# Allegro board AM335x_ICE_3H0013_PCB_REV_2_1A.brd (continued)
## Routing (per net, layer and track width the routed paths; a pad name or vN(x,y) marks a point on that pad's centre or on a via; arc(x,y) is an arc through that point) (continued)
N28737675: length 7.4
  TOP w0.121: U14.G17 33.05,42.45 32.71,42.11 31.47,42.11 30.86,41.5 30.13,41.5 29.97,41.34 29.97,40.93 28.8,39.75 R58.2
N28753994: length 11.2
  TOP w0.121: v1(22.35,97.59) 21.03,96.27 20.07,96.27 19.43,95.63 SW1.4
  BOTTOM w0.121: v1(22.35,97.59) U25.3 23.96,97.57 25.74,97.57 R100.2
N28754074: length 8.4
  TOP w0.121: v1(23.24,94.36) 24,94.36 24.51,93.85 SW1.8
  BOTTOM w0.121: U25.5 21.42,96.94 21.84,96.52 21.84,95.89 R87.2 22.1,95 22.48,94.61 22.99,94.61 v1(23.24,94.36)
N28785526: length 2.4
  BOTTOM w0.121: R112.2 J19.1
N28785533: length 2.7
  BOTTOM w0.121: 48.9,83.57 R110.2
N28944514: length 2.6
  BOTTOM w0.121: R114.2 61.47,84.33 J18.1
N28944521: length 2.7
  BOTTOM w0.121: R113.2 66.55,84.33 J18.3
N29141166: length 15.7
  TOP w0.121: U12.14 72.87,59.48 v1(72.34,58.95)
  BOTTOM w0.121: Y1.1 70.51,49.16 70.51,53.64 70.1,54.05 70.1,54.74 71.5,56.13 C89.2 71.5,58.11 v1(72.34,58.95)
N29141233: length 9.4
  TOP w0.121: v1(70.12,58.74) 69.38,59.48 U12.1
  BOTTOM w0.121: v1(70.12,58.74) 70.12,58.61 69.72,58.21 C90.2 68.83,56.9 Y1.2
N29141536: length 1.6
  TOP w0.121: R39.1 67.53,58.83 U12.2
N29149555: length 2.1
  TOP w0.121: R42.1 75.99,55.58 U12.8
N29149585: length 2.9
  TOP w0.121: U12.9 75.41,56.23 75.69,56.52 v1(75.69,56.9)
  BOTTOM w0.121: 75.44,58.04 75.44,57.15 v1(75.69,56.9)
N29149616: length 5.2
  TOP w0.121: v1(76.33,56.9) 75.69,57.53 U12.11
  BOTTOM w0.121: 74.3,58.04 74.3,57.53 75.44,56.39 75.82,56.39 v1(76.33,56.9)
N29208060: length 2.2
  TOP w0.121: J5.1 62.99,60.96 R37.1

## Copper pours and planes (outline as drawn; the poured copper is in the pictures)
DGND on TOP: 65.66,27.66 65.66,25.27 65.28,24.89 65.28,24.51 65.53,24.26 66.29,24.26 66.67,23.88 68.94,23.88 69.19,24.13 69.19,25.45 68.73,25.91 67.94,25.91 67.06,26.8 67.06,27.53 66.75,27.84 65.84,27.84
DGND on TOP: 41.17,22.62 40.64,22.1 38.73,22.1 36.91,23.92 36.91,25.93 37.18,26.2 38.14,26.2 38.99,25.34 40.93,25.34 41.17,25.11
DGND on TOP: 46.48,11.05 46.74,10.8 48.51,10.8 48.77,11.05 48.77,13.84 48.51,14.1 46.74,14.1 46.48,13.84
DGND on TOP: 67.31,60.58 74.8,60.58 75.56,59.82 74.68,58.93 67.31,58.93 67.06,59.18 67.06,60.33
DGND on TOP: 5.53,26.58 5.53,34.26 5.77,34.5 10.35,34.5 10.35,34.5 10.8,34.5 12.29,33.01 12.29,32.55 12.2,32.47 10.35,32.47 10.35,26.5 10.1,26.25 5.86,26.25
DGND on TOP: 40.26,54.23 40.39,54.1 40.39,52.2 39.75,51.56 38.48,51.56 38.1,51.94 38.23,52.07 38.23,53.72 38.86,54.36 38.99,54.23
DGND on TOP, BOTTOM: 53.39,51.91 53.39,52.87 53.75,53.24 54.19,53.24 54.34,53.09 54.34,52.84 53.83,52.33 53.83,52.33 53.73,52.23 53.73,51.91 53.7,51.87 53.42,51.87
DGND on BOTTOM: 37.34,46.86 37.34,45.34 37.97,44.7 37.97,44.2 37.72,43.94 36.96,43.94 36.7,43.69 36.7,42.93 36.96,42.67 37.34,42.67 37.34,42.16 37.47,42.04 38.35,42.04 38.42,42.1 39.12,41.4 40.13,41.4 40.51,41.78 41.27,41.78 42.29,40.77 42.93,40.77 42.93,48.26 40.77,48.26 40.01,47.5 39.12,47.5 38.73,47.88 38.35,47.88 38.23,47.75 38.23,47.24 38.1,47.12 37.59,47.12
DGND on BOTTOM: 36.14,54.05 35.87,54.32 35.87,55.12 37.5,56.75 37.5,58.71 36.6,57.81 35.36,57.81 35.36,58.23 36.32,59.19 40.2,59.19 40.69,59.68 40.69,63.43 36.9,63.43 36.07,64.26 36.07,64.26 35.14,65.19 33.1,65.19 32.41,65.88 32.41,67.33 32.73,67.64 32.89,67.64 32.89,72.9 33.08,73.09 33.15,73.03 33.15,73.53 33.4,73.79 34,73.79 35.56,72.22 35.56,71.37 36.45,70.48 36.45,66.93 37.21,66.17 43.18,66.17 43.43,66.42 44.32,66.42 44.32,66.89 47.29,69.86 47.83,69.86 47.82,69.86 54.72,69.86 55.84,70.98 60.75,70.98 61.4,70.33 63.11,70.33 66.66,66.78 66.66,63.4 67.98,62.08 75.08,62.08 76.27,60.89 76.27,56.46 75.08,56.46 74.54,56.99 74.54,58.67 73.58,59.63 67.24,59.63 63.09,63.78 63.09,67.58 62.44,68.24 48.89,68.24 47.29,66.64 47.29,65.12 45.98,63.81 44.32,63.81 44.32,60.71 45.34,60.71 46.1,59.94 46.1,59.69 44.32,57.91 44.32,56.77 44.07,56.52 43.31,56.52 43.08,56.29 43.08,55.82 41.31,54.05
DGND on BOTTOM: 68.63,59.49 72.57,59.49 73.28,58.78 73.28,45.72 72.26,44.7 67.82,44.7 66.8,45.72 66.8,50.42 65.53,51.69 65.53,52.83 66.04,53.34 66.04,56.9
DGND on BOTTOM: 63.25,6.35 63.75,6.35 64.39,6.99 64.77,6.99 65.79,8 65.79,8.26 65.53,8.51 63.12,8.51 62.99,8.38 62.99,6.6
DGND on BOTTOM: 49.15,10.8 49.66,11.3 49.66,12.95 45.72,12.95 45.59,12.83 45.59,11.18 45.97,10.8
DGND on BOTTOM: 43.97,44.55 44.12,44.55 44.68,45.11 47.42,45.11 47.32,45.21 50.8,45.21 55.2,49.61 58.5,49.61 59.24,48.87 61.31,48.87 61.79,48.39 62.97,48.39 62.97,48.38 63.42,48.38 65.72,46.09 66.42,46.09 66.58,45.93 66.58,44.84 66.55,44.81 68.76,42.59 68.76,37.95 68.15,37.34 67.82,37.34 67.31,36.83 67.31,35.31 69.62,35.31 69.62,33.76 68.15,33.76 68.11,33.73 66.5,33.73 66.12,34.11 66.12,37.52 62.69,40.94 62.69,42.38 61.62,43.45 57.71,43.45 56.24,41.98 56.24,39.1 56.29,39.1 56.83,38.56 56.83,35 56.52,34.69 56.88,34.33 56.88,31.34 57.95,30.27 58.63,30.95 67.59,30.95 67.59,30.13 67.06,29.59 64.9,29.59 64.01,28.7 57.45,28.7 53.85,32.3 53.85,40 51.89,41.96 47.74,41.96 47.34,42.36 47.34,42.47 47.17,42.47 46.2,43.43 44.7,43.43 44.42,43.15 44.02,43.15 43.87,43.31 43.87,44.45
DGND on BOTTOM: 40.16,11.96 40.16,9.33 40,9.17 40.02,9.17 39.17,8.32 39.17,4.82 40.14,3.85 43.2,3.85 44.16,4.82 44.16,7.86 43.67,8.36 43.67,11.96 43.47,12.16 40.37,12.16
DGND on LYR2_GND: 0.65,103.5 77.85,103.5 77.85,0.64 27.56,0.64 26.96,1.23 15.83,1.23 15.23,0.64 0.65,0.64
DGND on LYR4: 52.2,74.93 57.53,74.93 61.59,70.87 61.59,63.25 61.98,62.87 66.42,62.87 67.44,61.85 67.44,60.83 66.87,60.26 59.75,60.26 58.67,61.34 58.67,70.74 57.28,72.14 56.77,72.14 55.63,73.28 51.94,73.28 51.56,73.66 51.56,74.3
GND_EARTH on TOP: 1.4,0.76 1.4,5.08 2.03,5.72 3.68,5.72 4.19,5.21 4.19,3.56 3.17,2.54 3.17,0.76
GND_EARTH on TOP: 9.53,0.64 9.53,2.67 8.64,3.56 8.64,4.32 9.02,4.7 10.92,4.7 11.05,4.57 11.05,2.41 11.43,2.03 11.43,0.64
GND_EARTH on BOTTOM: 28.27,0.82 27.74,1.34 14.89,1.34 14.43,0.89 2.92,0.89 1.65,2.16 1.65,5.46 2.02,5.83 2.65,5.83 3.05,6.22 3.05,7.29 3.12,7.36 4.35,7.36 4.48,7.23 4.48,4.93 4.97,4.45 7.38,4.45 8.52,5.59 10.41,5.59 11.94,7.11 13.72,7.11 14.22,7.62 14.22,11.94 18.54,16.26 29.08,16.26 29.97,15.37 29.97,11.79 29.54,11.36 28.89,11.36 28.07,12.19 28.07,12.95 27.3,13.72 20.95,13.72 20.26,13.02 19.11,13.02 18.41,12.32 16.26,12.32 15.49,11.56 15.49,5.97 14.22,4.7 11.18,4.7 10.92,4.45 10.92,2.67 11.18,2.41 27.98,2.41 28.27,2.12 30.4,2.12 30.62,1.9 30.62,0.96 30.48,0.82
GND_EARTH on LYR2_GND: 1.27,2.03 2.16,1.14 13.34,1.14 14.2,2.01 30.14,2.01 30.48,1.67 30.48,0.51 27.56,0.51 27.05,1.02 15.75,1.02 15.24,0.51 1.18,0.51 0.64,1.05 0.64,24.81 0.72,24.89 1.02,24.89 1.27,24.64
GND_EARTH on LYR5_PWR: 0.77,24.89 1.02,24.89 1.27,24.64 1.27,3.19 3.31,1.14 13.34,1.14 13.97,1.78 27.94,1.78 28.32,2.16 30.35,2.16 30.48,2.03 30.48,0.51 27.56,0.51 27.05,1.02 15.75,1.02 15.24,0.51 0.91,0.51 0.66,0.76 0.66,24.78
GND_OSC1 on BOTTOM: 42.16,26.16 42.16,32.26 42.42,32.51 50.29,32.51 50.55,32.26 50.55,26.16 50.29,25.91 42.42,25.91
GNDA_ADC on LYR4: 39.62,37.34 39.88,37.08 40.39,37.08 40.64,37.34 40.64,39.75 41.15,40.26 41.15,40.51 41.02,40.64 40.26,40.64 39.62,40.01
GNDPROFI on LYR5_PWR: 1.27,25.15 5.59,25.15 6.1,25.65 6.1,33.27 6.6,33.78 10.92,33.78 11.43,34.29 11.43,37.08 12.83,38.48 18.67,38.48 20.7,40.51 20.7,45.34 17.02,49.02 9.4,49.02 8.89,49.53 8.89,53.59 9.4,54.1 18.54,54.1 19.05,53.59 19.05,52.58 19.56,52.07 23.62,52.07 24.13,52.58 24.13,57.15 23.62,57.66 17.02,57.66 16.51,58.17 16.51,60.96 16,61.47 7.92,61.47 7.65,61.2 7.65,57.04 6.88,56.27 4.97,56.27 4.7,56.01 1.27,56.01
V3_3D on TOP: 61.72,27.69 62.87,27.69 63.75,26.8 65.15,26.8 65.28,26.67 65.28,25.4 64.77,24.89 64.77,24.38 64.52,24.13 61.98,24.13 61.47,24.64 61.47,27.43
V3_3D on TOP: 67.18,56.39 66.67,55.88 66.67,55.24 66.17,54.74 66.17,54.48 66.29,54.36 68.45,54.36 69.34,55.24 69.34,55.37 69.47,55.37 69.47,56.39
V3_3D on BOTTOM: 64.9,25.78 63.12,25.78 62.99,25.91 62.99,27.18 62.74,27.43 61.85,27.43 61.72,27.3 61.72,24.51 61.85,24.38 62.87,24.38 62.99,24.51 62.99,24.64 63.25,24.89 64.9,24.89
V3_3D on LYR5_PWR: 4.45,56.26 1.27,56.26 1.27,102.87 77.22,102.87 77.22,10.92 76.83,10.54 61.72,10.54 56.39,5.21 51.05,5.21 49.53,6.73 49.53,23.98 48.62,24.89 27.94,24.89 25.61,22.55 25.61,22.44 23.19,20.02 11.13,20.02 9.06,17.95 2.88,17.95 1.52,19.31 1.52,24.64 1.78,24.89 5.84,24.89 6.35,25.4 6.35,33.02 6.86,33.53 11.18,33.53 11.68,34.04 11.68,36.83 12.67,37.82 17.75,37.82 17.78,37.85 17.78,48.77 17.27,49.28 9.65,49.28 9.14,49.78 9.14,53.34 9.65,53.85 18.29,53.85 18.8,53.34 18.8,52.32 19.3,51.82 23.88,51.82 24.38,52.32 24.38,61.21 19.56,66.04 5.59,66.04 5.08,65.53 5.08,56.9 ; 1 cut-out
V5_0D on TOP: 33.53,20.48 33.53,15.37 32.64,14.48 30.73,14.48 30.54,14.67 30.54,18.35 30.86,18.67 30.86,25.27 31.11,25.53 34.04,25.53 34.29,25.27 34.29,21.25
V5_0D on TOP: 25.15,7.49 25.15,8.26 23.24,8.26 22.11,7.12 19.81,7.12 19.81,6.48 22.73,6.48 23.75,7.49
V5_0D on TOP: 64.39,14.48 64.39,15.88 64.64,16.13 64.64,17.75 65.68,18.8 66.67,18.8 66.71,18.76 66.99,18.76 67.61,18.14 67.61,16.94 66.04,15.37 66.04,14.61 65.91,14.48
V5_0D on TOP: 16.76,7.11 16.76,5.97 16.51,5.72 16.51,4.7 16.26,4.45 14.61,4.45 14.35,4.19 14.35,4.1 13.26,4.1 13.26,5.24 13.6,5.59 15.75,5.59 16.13,5.97 16.13,7.11
V5_0D on TOP: 46.14,25.01 47.87,25.01 48.26,25.4 50.29,25.4 50.42,25.27 50.42,24.13 49.02,22.73 47.12,22.73 46.86,22.99 46.86,24 46.54,24.32 46.08,24.32 45.91,24.49 45.91,24.78
V5_0D on BOTTOM: 66.93,16.13 66.93,15.75 66.8,15.62 65.41,15.62 65.15,15.88 65.15,18.67 65.41,18.92 66.8,18.92 66.92,18.81 66.94,18.81 67.61,18.14 67.61,16.81
V5_0D on BOTTOM: 31.95,24.44 32.37,24.44 32.37,23.13 32.42,23.08 33.38,23.08 33.41,23.12 33.41,24.44 33.78,24.44 33.78,22.73 34.17,22.35 34.17,21.29 34.11,21.22 30.93,21.22 30.67,21.49 30.67,22.67 30.42,22.92 29.91,22.92 29.72,23.11 29.72,24.64 29.84,24.77 31.62,24.77
V5_0D on BOTTOM: 71.25,36.79 71.89,37.43 77.02,37.43 77.2,37.25 77.2,36.97 77.22,36.96 77.22,22.73 74.68,20.19 67.44,20.19 67.44,20.45 65.66,22.23 65.28,22.23 65.15,22.35 63.5,22.35 63.5,23.11 65.28,23.11 65.41,23.24 65.41,27.05 65.15,27.3 65.15,28.96 65.41,29.21 66.93,29.21 67.69,28.45 67.69,25.78 68.96,24.51 68.96,21.97 71.37,21.97 71.75,22.35 71.75,28.7 72.39,29.34 72.39,34.8 71.25,35.94
V5_0D on LYR3: 72.01,37.42 72.33,37.74 76.95,37.74 77.22,37.47 77.22,10.48 74.58,7.85 72.76,7.85 72.28,7.36 72.28,7.35 72.25,7.35 72.23,7.33 69.78,7.33 68.45,8.66 68.45,15.11 67.44,16.13 66.93,16.13 66.67,15.88 65.35,15.88 65.13,16.1 65.13,16.97 65.79,17.63 65.79,18.54 66.04,18.8 66.93,18.8 67.18,18.54 67.94,18.54 68.45,19.05 68.45,22.99 72.01,26.54
V5_0D on LYR4: 77.23,55.75 77.23,34.75 76.93,34.45 73.03,34.45 73.03,34.45 72.66,34.45 71.94,35.16 71.94,36.68 72.45,37.18 72.45,46.49 74.44,48.49 74.44,51.56 73.66,52.34 73.66,55.24 73.79,55.37 73.79,76.2 72.64,77.34 69.6,77.34 69.22,77.72 69.22,82.93 69.98,83.69 77.34,83.69 77.66,83.38 77.66,76.83 76.96,76.14 76.96,56.02
V5_0D on LYR5_PWR: 44.69,25.15 48.77,25.15 49.28,24.64 49.28,18.03 48.77,17.53 48.77,16.89 49.28,16.38 49.28,6.22 50.8,4.7 56.64,4.7 61.98,10.03 77.22,10.03 77.22,1.91 76.58,1.27 31.24,1.27 30.35,2.16 13.84,2.16 13.08,1.4 12.09,1.4 12.09,11.96 14.44,14.31 22.84,14.31 24.9,14.3 27.24,16.64 28.26,17.51 30.49,19.74 30.49,21.59 30.48,21.6 30.48,22.05 31.09,22.66 32.83,22.66 33.17,22.32 41.87,22.32
V13 on TOP: 62.23,10.03 62.23,8 62.74,7.49 65.15,7.49 65.41,7.75 65.41,8.89 65.15,9.14 63.63,9.14 63.25,9.53 63.25,9.65 62.74,10.16 62.36,10.16
V13 on BOTTOM: 67.06,14.73 67.06,10.03 66.04,9.02 63.12,9.02 62.69,8.59 62.48,8.59 62.33,8.74 62.33,10.01 62.87,10.54 66.22,10.54 66.29,10.62 66.29,12.45 65.91,12.83 65.91,14.73 66.17,14.99 66.8,14.99
V24_0HVS on BOTTOM: 45.52,6.65 45.52,5.64 46.28,4.88 47.96,4.88 48.06,4.98 48.06,7.06 48.01,7.11 46.02,7.11 45.57,6.65
V24_0HVS on BOTTOM: 42.16,20.7 42.16,24.38 42.42,24.64 46.23,24.64 46.61,24.26 46.61,22.1 46.86,21.84 49.15,21.84 49.28,21.72 49.28,20.32 48.51,19.56 45.47,19.56 45.09,19.18 45.09,17.78 45.47,17.4 49.53,17.4 50.04,16.89 50.04,15.11 49.91,14.99 45.47,14.99 44.32,16.13 40.39,16.13 40.01,16.51 40.01,19.3 40.64,19.94 41.4,19.94
V24_0HVS on LYR3: 47.07,10.37 47.07,7.34 46.48,6.75 45.42,6.75 45.38,6.71 45.38,5.92 48.55,2.75 62.02,2.75 65.34,6.08 67.76,6.08 68.49,5.35 68.51,5.35 69.57,4.29 69.57,2.36 70.4,1.53 74.57,1.53 74.88,1.83 74.88,6.56 74.59,6.85 73.14,6.85 73.13,6.85 69.39,6.85 68.65,7.59 62.36,7.59 61.03,6.26 52.3,6.26 51.28,7.27 51.28,13.04 49.93,14.39 49.88,14.39 49.24,15.03 49.24,18.88 47.39,20.73 44.59,20.73 44.31,20.45 41.49,20.45 40.73,19.69 40.73,16.71
V24_0HVS on LYR4: 72.1,21.84 72.1,21.42 69.88,19.2 69.88,3.08 71.46,1.5 74.68,1.5 75.39,2.21 75.39,21.07 74.41,22.05 72.31,22.05
V24_IN on TOP: 41.04,9.27 42.55,9.27 44.45,7.37 45.97,7.37 46.35,7.75 46.35,10.54 45.47,11.43 40.8,11.43 39.85,12.38 35.64,12.38 35.24,11.97 35.24,12 34.22,10.99 34.22,7.78 35.1,6.9 38.04,6.9 38.06,6.91 38.68,6.91
V24_IN on BOTTOM: 38.1,9.12 36,7.02 34.33,7.02 33.29,8.07 33.29,10.63 33.3,10.63 33.3,11.05 34.3,12.05 34.73,12.05 35.06,12.38 35.06,14.12 35.32,14.38 37.8,14.38 38.1,14.07
V24_IN on LYR3: 8.44,20.38 8.81,20.75 9.91,20.75 10.06,20.6 10.06,19.93 9.61,19.47 9.54,19.4 9.54,18 10.87,16.67 10.98,16.78 11.86,16.78 12.74,15.91 35.78,15.91 39.48,12.21 43.48,12.21 46.37,9.32 46.37,8.5 45.82,7.95 44.29,7.95 42.75,9.49 39.4,9.49 38.2,8.28 36.22,8.28 30.13,14.37 11.42,14.37 8.44,17.35
V24_IN on LYR4: 8.32,20.68 8.32,18.35 8.46,18.2 9.72,18.2 10.08,18.55 10.08,20.49 9.85,20.72 9.85,21.96 6.9,24.9 6.9,55.08 1.8,60.19 1.8,94.26 2.02,94.48 3.33,94.48 3.52,94.29 3.52,93.29 4.21,92.61 6.12,92.61 7.09,93.57 7.09,95.93 6.68,96.34 1.69,96.34 0.7,95.36 0.7,58.32 5.03,53.99 5.03,51.46 4.49,50.91 4.49,33.03 5.14,32.37 5.14,25.29 5.03,25.18 5.03,23.97
VDD1_SMPS on TOP: 30.59,7.52 30.59,10.67 33.13,13.22 33.13,14.35 33.52,14.73 35.35,14.73 35.6,14.49 35.6,13.34 33.61,11.36 33.61,9.25 31.79,7.43 30.68,7.43
VDD1_SMPS on BOTTOM: 32,14.35 32,12.7 32.26,12.45 34.52,12.45 34.68,12.61 34.68,14.47 34.54,14.61 32.26,14.61
VDD1_SMPS_AM335X on BOTTOM: 32,17.27 32,15.24 34.59,15.24 34.77,15.43 34.77,17.19 34.72,17.24 34.69,17.24 34.54,17.4 32.13,17.4
VDD1_SMPS_AM335X on BOTTOM: 35.69,36.32 36.07,36.7 37.21,36.7 37.47,36.96 37.47,39.75 37.59,39.88 37.97,39.88 38.23,40.13 38.23,41.59 37.85,41.4 37.34,41.4 37.34,42.16 37.08,42.42 36.07,42.42 35.94,42.29 35.94,41.78 36.07,41.66 36.7,41.66 36.7,40.89 35.56,39.75 35.56,38.86 35.31,38.61 33.91,38.61 33.66,38.35 33.66,36.7 32,35.05 32,33.66 32.26,33.4 32.77,33.4 32.77,33.66 33.15,34.04 34.67,34.04 34.67,35.18 36.58,35.18 36.58,35.81 36.45,35.94 35.81,35.94 35.69,36.07
VDD1_SMPS_AM335X on LYR4: 33.68,15.09 33.2,15.57 33.2,16.74 33.78,17.32 35.36,17.32 35.38,17.3 35.43,17.3 35.76,17.63 35.91,17.63 35.91,20.33 35.34,20.9 34.12,20.9 33.44,21.58 32.56,21.58 30.91,23.23 30.91,34.05 32.08,35.22 32.78,35.22 33.19,34.81 33.19,33.71 32.92,33.43 32.92,33.4 32.45,32.93 32.45,25.47 34.1,23.82 34.1,22.14 34.59,21.65 35.8,21.65 37.3,20.15 37.3,17.08 35.31,15.09
VDD2_SMPS on TOP: 27.39,20.6 29.83,20.6 30.02,20.41 30.02,19.15 29.63,18.77 29.03,18.77 28.49,19.3 27.43,19.3 27.39,19.34
VDD2_SMPS on BOTTOM: 31.12,18.38 28.3,18.38 27.78,18.9 27.78,19.65 28.37,20.24 29.07,20.24 29.73,19.58 31.12,19.58
VDD2_SMPS_AM335X on BOTTOM: 34.62,18.41 35.46,19.25 35.46,20.12 35.26,20.32 34.66,20.32 34.53,20.19 34.53,19.86 34.22,19.56 32.01,19.56 31.98,19.52 31.98,18.51 32.07,18.41
VDD2_SMPS_AM335X on BOTTOM: 28.08,45.03 28.08,44.19 27.8,43.91 27.8,42.54 28.38,41.96 28.57,41.96 29.21,42.6 30,42.6 30.03,42.63 30.03,43 30.02,43.01 29.56,43.01 29.46,43.11 29.46,45.04 29.47,45.05 28.3,45.05 28.28,45.03
VDD2_SMPS_AM335X on LYR3: 43.18,47.57 43.18,41.3 42.65,40.77 33.4,40.77 32.51,39.88 29.8,39.88 29.51,39.58 28.13,39.58 27.47,40.25 27.47,43.27 27.63,43.43 34.54,43.43 35.26,44.15 35.26,44.45 35.14,44.56 35.14,46.95 35.31,47.12 37.97,47.12 38.99,48.13 42.62,48.13
VDD2_SMPS_AM335X on LYR4: 28.18,21.94 27.82,22.3 27.82,30.99 27.56,31.25 27.56,33 27.56,33 27.82,33.27 27.82,39.03 27.94,39.14 27.94,40.39 28.28,40.73 28.28,41.08 28.02,41.34 28,41.34 27.31,42.04 27.31,43.33 27.55,43.57 29.14,43.57 30.65,42.07 30.65,39.16 29.59,38.1 28.95,38.1 28.95,22.78 31.41,20.32 35.15,20.32 35.36,20.12 35.36,18.44 35.2,18.29 33.96,18.29 33.95,18.28 30.54,18.28 28.18,20.63
VDD_LED on TOP: 63.63,55.24 63.63,53.72 64.14,53.21 65.66,53.21 66.04,53.59 66.04,54.1 64.77,55.37 63.75,55.37
VDD_LED on TOP: 48.77,27.08 48.77,25.96 48.97,25.76 51.82,25.76 52.53,26.47 52.53,27.48 52.17,27.84 51.92,27.84 51.31,27.23 49.07,27.23 49.07,27.23 48.92,27.23
VDD_LED on LYR3: 67.18,54.36 67.44,54.61 67.44,56.13 67.18,56.39 64.9,56.39 64.64,56.13 64.14,56.13 63.5,55.5 63.5,54.23 64.39,53.34 66.93,53.34 67.18,53.59
VDDA_ADC on TOP: 37.03,29.11 37.03,30.99 37.58,31.53 38.4,31.53 39.07,32.21 39.78,32.21 39.88,32.11 39.88,31.6 39.12,30.84 39.01,30.84 38.66,30.48 38.66,29.11 38.61,29.06 37.08,29.06
VDDS_DDR on TOP: 8.94,7.8 7.16,7.8 7.07,7.7 7.07,6.44 7.75,5.76 9.6,5.76 9.74,5.89 9.74,6.08 9.54,6.27 9.32,6.27 9.05,6.54 9.05,7.68
VDDS_DDR on TOP: 52.58,36.96 52.58,33.48 52.83,33.22 53.04,33.22 53.16,33.35 53.16,33.45 53.04,33.58 53.04,35.15 53.34,35.46 53.34,36.96 53.21,37.08 52.7,37.08
VDDS_DDR on TOP: 65.38,41.06 66.53,41.06 67.45,40.14 67.45,32.6 68.52,31.54 68.52,30.43 68.43,30.34 67.33,30.34 66.23,31.44 66.23,38.41 65.79,38.85 65.22,38.85 65.22,40.9
VDDS_DDR on BOTTOM: 43.18,48.03 43.18,45.59 43.05,45.47 43.05,45.09 43.18,44.96 43.18,43.94 43.05,43.81 43.05,43.43 43.18,43.31 43.18,42.29 43.05,42.16 43.05,41.91 43.18,41.78 43.18,40.77 43.05,40.64 43.05,40.26 43.18,40.13 43.67,40.13 43.81,40.28 43.81,44.96 44.78,45.92 44.78,47.7 44.45,48.03
VDDS_DDR on LYR5_PWR: 1.83,3.31 1.86,12.13 1.87,12.13 1.87,12.52 1.88,12.53 1.88,13.43 5.83,17.39 9.63,17.39 11.36,19.12 23.96,19.12 26.29,21.45 26.29,22.18 26.27,22.2 26.27,23.47 28.31,25.5 35.47,25.5 36.77,26.81 36.77,31.62 43.05,37.9 43.05,47.2 45.03,49.17 45.05,49.17 45.85,49.97 45.85,50.54 47.93,52.62 48.1,52.62 51.24,55.75 63.37,55.75 66.54,52.59 66.54,40.78 66.53,40.78 66.53,38.8 62.95,35.21 55.28,35.21 53.18,33.12 50.19,33.12 49.49,32.41 49.47,32.41 44.34,27.28 44.34,25.67 41.41,22.74 33.65,22.74 33.17,23.22 30.94,23.22 29.77,22.05 29.77,20.01 29.38,19.62 29.38,19.59 24.67,14.88 13.87,14.88 11.67,12.68 11.67,2.34 11.08,1.75 3.39,1.75
PH on TOP: 40.39,15.49 40.39,17.53 40.64,17.78 42.42,17.78 42.67,18.03 42.67,18.29 42.93,18.54 43.94,18.54 44.2,18.29 44.2,13.97 43.94,13.72 42.93,13.72 42.67,13.97 42.67,14.99 42.42,15.24 40.64,15.24
PWR_SWIO on TOP: 13.72,11.18 13.93,11.39 15.03,11.39 15.03,11.56 14.1,11.56 12.7,12.95 8.89,12.95 8.89,11.94 12.19,11.94 12.95,11.18
PWR_VDD1_SMPS on TOP: 18.41,5.92 18.41,5.64 19.35,4.7 22.86,4.7 23.24,4.32 23.24,3.3 23.5,3.05 28.7,3.05 28.96,3.3 28.96,4.83 30.48,6.35 31.62,6.35 31.62,3.56 30.35,3.56 30.1,3.3 30.1,2.29 29.84,2.03 22.86,2.03 22.16,2.73 22.16,3.75 21.59,4.32 19.05,4.32 18.03,5.33 18.03,5.82 18.14,5.92 18.41,5.92
PWR_VDD2_SMPS on TOP: 20.7,10.41 20.7,10.16 21.97,10.16 23.11,11.3 23.11,14.35 23.37,14.61 26.8,14.61 26.92,14.73 26.92,16.76 27.18,17.02 27.94,17.02 28.19,17.27 28.19,18.5 25.4,18.5 25.4,15.75 23.24,15.75 22.61,15.11 22.61,11.56 21.46,10.41
PWR_VDDS_DDR on TOP: 13.34,10.29 13.84,10.29 14.1,10.54 15.07,10.54 15.07,10.8 8.26,10.8 7.87,10.41 7.87,9.36 9.48,7.75 9.48,6.71 9.55,6.65 12.84,6.65 12.89,6.7 12.89,9.84
USB_DC on TOP: 4.41,6.31 4.41,6.16 4.58,6 4.58,5.57 4.58,5.31 4.85,5.03 4.85,3.57 4.86,3.57 5.24,3.57 5.24,6.3 5.17,6.38 4.48,6.38
USB_DC on BOTTOM: 14.51,34.4 14.51,32.97 15.23,32.26 16.85,32.26 16.85,30.85 17.3,30.85 17.4,30.95 17.4,32.69 17.12,32.97 15.83,32.97 15.51,33.28 15.51,34.36 15.39,34.48 14.59,34.48
USB_DC on BOTTOM: 4.89,6.62 7.06,6.62 7.15,6.52 7.15,5.36 6.94,5.15 4.9,5.15 4.82,5.23 4.82,6.55
VADD33_PRUETH0 on TOP: 51.71,84.7 51.71,83.11 52.14,82.68 52.58,82.68 52.75,82.51 52.75,81.92 53.03,81.64 53.5,81.64 53.6,81.75 53.6,82.03 53.3,82.33 53.3,85.12 53.15,85.27 51.88,85.27 51.7,85.08 51.7,84.72
VADD33_PRUETH0 on BOTTOM: 51.68,82.29 52.92,82.29 53.27,82.64 53.27,85.05 52.9,85.42 51.74,85.42 50.46,84.14 50.46,84.12 47.88,81.53 47.88,80.26 48.13,80.01 49.4,80.01
VADD33_PRUETH1 on BOTTOM: 32.33,82.86 32.89,82.3 35.81,82.3 36.45,82.93 36.45,84.84 35.81,85.47 35.23,85.47 35.08,85.33 35.08,84.91 34.82,84.64 32.4,84.64 32.33,84.57
VAUX1 on BOTTOM: 22.1,19.91 22.1,21.18 21.84,21.44 21.84,22.1 22.2,22.45 22.2,23.52 22.35,23.67 22.81,23.67 23.16,23.32 23.16,19.86 23.11,19.81 22.05,19.81 22.05,19.86
VAUX1 on LYR4: 34.54,23.37 34.54,22.56 34.9,22.2 35.66,22.2 35.86,22.4 35.86,23.11 35,23.98 34.54,23.98 34.44,23.88 34.44,23.47
VAUX2 on TOP: 27.37,33.46 27.37,35.5 27.56,35.69 29.97,35.69 30.1,35.56 30.1,34.67 29.66,34.23 28.42,34.23 27.96,33.77 27.96,33.4 27.83,33.27 27.56,33.27
VAUX2 on TOP: 24.22,23.81 24.22,21.26 24.44,21.04 24.89,21.04 25,21.15 25,21.96 25.3,22.26 25.93,22.26 26.17,22.5 26.17,23.74 25.96,23.95 24.36,23.95
VAUX2 on BOTTOM: 31.88,41.4 31.88,40.89 32.13,40.64 33.27,40.64 33.66,41.02 34.92,41.02 35.05,40.89 35.56,40.89 35.69,41.02 35.69,42.29 35.56,42.42 35.18,42.42 35.05,42.29 35.05,42.04 34.92,41.91 32.89,41.91 32.38,41.4
VAUX2 on BOTTOM: 62.43,21.89 62.43,21.03 62.79,20.68 64.92,20.68 65.33,21.08 65.33,21.84 65.23,21.95 62.48,21.95
VAUX2 on BOTTOM: 28.14,37.74 28.14,34.34 28.4,34.09 29.67,34.09 30.23,34.65 30.23,35.51 29.92,35.81 29.11,35.81 28.96,35.97 28.96,37.54 28.65,37.85 28.24,37.85
VAUX2 on BOTTOM: 41.66,48.39 43.81,48.39 43.94,48.51 43.94,50.42 44.41,50.88 44.41,51.69 42.34,51.69 41.91,51.26 41.91,48.9 41.66,48.64
VAUX2 on BOTTOM: 34.42,45.72 35.05,45.72 35.05,46.1 35.43,46.1 35.43,45.21 34.92,44.7 33.53,44.7 33.02,45.21 32.13,45.21 32.13,46.61 32.77,46.61 33.4,45.97 34.16,45.97
VAUX2 on BOTTOM: 35.56,50.29 35.56,49.15 36.07,48.64 36.07,48.39 36.2,48.26 36.96,48.26 37.08,48.39 37.08,48.51 36.7,48.9 36.7,50.8 36.41,51.09 36.41,51.69 34.92,51.69 34.92,50.93
VAUX2 on LYR4: 35.76,28.09 35.76,27.69 35.56,27.48 35.56,27.08 35.66,26.97 36.17,26.97 36.47,27.28 36.47,27.89 36.17,28.19 35.86,28.19
VAUX2 on LYR5_PWR: 29.54,34.44 29.54,35.5 30.9,36.86 30.9,47.6 32.21,48.91 34.51,51.21 37.99,51.21 40.4,53.62 40.4,53.67 43.75,57.02 47.53,57.02 50.28,59.77 55.2,59.77 55.88,60.45 55.88,63.12 55.23,63.77 46.59,63.77 45.34,65.02 45.34,66.8 45.85,67.31 52.7,67.31 53.21,66.8 54.1,66.8 54.61,67.31 65.15,67.31 65.91,66.55 65.91,56.66 65.52,56.26 50.93,56.26 45.47,50.79 45.47,50.16 44.5,49.2 44.56,49.2 42.8,47.44 42.8,37.96 38.88,34.04 38.62,34.04 36.26,31.68 36.26,27.13 35.2,26.07 28.13,26.07 25.81,23.75 25.81,21.62 23.95,19.76 12.22,19.76 11.78,20.2 11.78,20.85 12.5,21.57 16.93,21.57 17.41,21.08 20.45,21.08 22.11,22.74 22.11,23.96 25.64,27.49 28.21,27.49 30.18,29.46 30.18,33.8
VAUX33 on BOTTOM: 17.88,19.71 17.88,20.73 17.42,21.18 17.42,22.15 17.63,22.35 18.9,22.35 19.2,22.05 19.2,19.71 19.15,19.66 17.93,19.66
VAUX33 on BOTTOM: 69.44,38.2 70.51,38.2 70.61,38.1 70.61,35.81 70.46,35.66 69.19,35.66 69.19,37.08 69.44,37.34
VAUX33 on LYR3: 30.05,48.22 30.05,47.17 30.25,46.96 30.77,46.96 31.87,48.06 31.87,48.32 33.09,49.54 33.71,49.54 33.91,49.74 33.91,50.28 33.67,50.52 32.34,50.52
VCAN0 on TOP: 5.46,37.85 8.38,37.85 9.65,39.12 17.14,39.12 17.53,39.5 17.53,44.7 19.43,46.61 20.45,46.61 20.83,46.23 20.83,43.56 22.61,41.78 22.61,36.95 22.29,36.64 20.73,36.64 20.19,37.17 20.19,38.48 15.49,38.48 14.41,37.4 9.47,37.4 9.16,37.08 5.33,37.08 5.33,37.72
VDAC on TOP: 10.87,16.92 10.87,18.34 10.97,18.44 10.97,18.8 11.13,18.95 12.5,18.95 12.6,18.85 12.6,18.59 12.24,18.24 12.14,18.24 11.99,18.08 11.99,16.87 10.92,16.87
VDAC on BOTTOM: 33.27,38.86 33.53,39.12 34.92,39.12 35.18,39.37 35.18,39.75 35.31,39.88 35.56,39.88 35.69,40.01 35.69,40.64 35.56,40.77 34.92,40.77 34.8,40.89 33.4,40.89 32.77,40.26 32.13,40.26 32.13,38.86
VDAC on BOTTOM: 34.42,51.69 33.91,51.69 33.91,51.05 33.66,50.8 33.02,50.8 32.89,50.67 32.89,49.66 33.27,49.28 34.04,49.28 34.04,48.64 34.54,48.13 35.56,48.13 35.69,48.26 35.69,48.64 35.56,48.64 35.18,49.02 35.18,50.16 34.42,50.93
VDAC on BOTTOM: 20.6,32.28 21.69,31.19 26.87,31.19 26.87,32.77 27.18,33.07 30.63,33.07 31.65,34.09 31.65,34.85 31.45,35.05 31.19,35.05 30.02,33.88 26.97,33.88 26.11,33.02 20.8,33.02 20.6,32.82
VDAC on BOTTOM: 41.53,50.73 41.21,51.05 41.21,51.69 40.73,51.69 40.73,51.05 40.39,50.71 40.39,49.15 40.01,48.77 40.01,48.39 40.13,48.26 40.89,48.26 41.53,48.9
VDAC on LYR3: 11.07,18.29 12.5,18.29 12.85,18.64 12.85,20.37 12.75,20.47 11.28,20.47 10.97,20.17 10.97,18.44 11.07,18.34
VDAC on LYR4: 19.25,24.54 18.85,24.94 18.85,25.1 19.61,25.86 19.61,32.77 20.12,33.27 21.03,33.27 21.49,32.82 21.49,30.78 21.08,30.38 21.08,25.91 19.71,24.54
VDAC on LYR4: 42.29,41.15 42.04,40.89 39.93,40.89 39.22,40.18 39.22,39.27 39.07,39.12 36.83,39.12 36.07,39.88 35.31,39.88 35.05,40.13 35.05,40.77 35.53,41.25 38.58,41.25 38.96,41.63 38.96,42.11 38.53,42.55 36.96,42.55 36.7,42.8 36.7,43.69 36.45,43.94 35.43,43.94 35.43,48.01 35.18,48.26 35.18,48.51 35.31,48.64 35.43,48.64 35.56,48.51 36.2,48.51 36.58,48.9 42.04,48.9 42.29,48.64
VDIG2 on BOTTOM: 37.59,51.69 37.59,51.05 37.21,50.67 37.21,48.77 37.72,48.26 37.85,48.26 38.73,49.15 38.73,49.4 38.35,49.78 38.35,50.29 38.86,50.8 39.24,50.8 39.5,51.05 39.5,51.69
VDIG2 on BOTTOM: 42.42,40.39 42.01,40.79 39.88,40.79 39.67,41 39.01,41 38.91,40.89 38.91,40.49 39.32,40.08 40.18,40.08 40.59,39.67 41.05,39.67 41.15,39.57 41.15,36.96 43.05,35.05 43.69,35.05 43.69,35.94 42.42,37.21
VDIG2 on BOTTOM: 15.85,19.71 15.85,21.39 15.49,21.74 15.49,22.2 15.7,22.4 16.66,22.4 17.07,22 17.07,19.76 16.97,19.66 15.9,19.66
VDIG2 on LYR4: 35.18,43.18 35.19,43.17 35.78,43.17 36.53,42.42 37.74,42.42 38.4,41.76 38.4,41.55 37.9,41.05 37.85,41.05 37.49,41.4 34.54,41.4 34.42,41.53 34.04,41.53 33.53,42.04 33.53,43.05 33.66,43.18
VMMC on BOTTOM: 33.27,44.07 33.4,44.2 35.18,44.2 35.43,43.94 35.43,42.8 35.05,42.8 35.05,42.93 34.8,43.18 34.29,43.18 33.91,42.8 32.13,42.8 32.13,43.43 29.84,43.43 29.59,43.69 29.59,46.1 29.08,46.61 27.43,46.61 27.18,46.86 27.18,48.9 27.43,49.15 28.96,49.15 29.01,49.1 29.01,48.46 29.26,48.21 29.87,48.21 30.23,47.85 30.23,44.2 30.35,44.07
VMMC on BOTTOM: 20.02,19.76 20.02,21.54 20.98,22.5 20.98,22.71 21.49,23.22 21.69,23.22 21.95,22.96 21.95,22.71 21.39,22.15 21.39,20.22 20.93,19.76
VMMC on LYR4: 20.98,39.78 19.41,39.78 19.25,39.62 19.25,38.96 19.46,38.76 20.93,38.76 21.18,39.01 21.18,39.57
VMMC on LYR4: 28.7,48.21 29.77,48.21 29.87,48.11 29.87,47.19 29.62,46.94 28.96,46.94 28.65,47.24 28.65,48.16
VPROFI_SRC on LYR5_PWR: 24.13,60.96 24.13,58.42 23.62,57.91 17.27,57.91 16.76,58.42 16.76,61.21 16.26,61.72 7.52,61.72 7.51,61.72 7.51,61.58 6.88,60.96 6.88,57.19 6.66,56.96 5.16,56.96 4.46,56.26 1.38,56.26 1.21,56.42 1.21,65.45 1.55,65.79 19.3,65.79
VRTC on TOP: 22.71,46.74 23.11,46.33 23.72,46.33 23.88,46.48 23.88,47.6 23.93,47.65 25.32,47.65 25.48,47.8 25.48,49.5 25.35,49.63 23.06,49.63 22.71,49.28
VRTC on BOTTOM: 34.16,27.18 34.67,27.18 35.31,26.54 35.31,25.4 34.92,25.02 33.53,25.02 33.15,25.4 33.15,26.54 32.97,26.72 26.77,26.72 26.11,26.06 24.84,26.06 24.38,26.52 24.38,27.43 24.64,27.69 33.66,27.69
VRTC on LYR4: 42.04,39.88 41.53,39.88 41.27,39.62 41.27,36.96 41.25,36.93 41.25,35.97 41.72,35.5 42.21,35.5 42.53,35.81 42.53,35.82 42.6,35.89 42.6,37.47 42.29,37.77 42.29,39.62
VTT_DDR on TOP: 64.39,32.57 64.39,32.3 64.64,32.05 66.29,32.05 66.4,31.95 66.4,30.58 66.24,30.43 63.76,30.43 63.44,30.75 58.17,30.73 56.39,30.73 55.96,31.17 55.96,33.1 56.89,34.04 59.18,34.04 59.44,33.78 59.44,32.84 59.62,32.66 64.29,32.66
VTT_DDR on BOTTOM: 68.33,33.53 68.45,33.4 68.45,32.38 68.2,32.13 68.2,32 67.56,31.37 65.02,31.37 64.39,30.73 57.66,30.73 57.4,30.99 57.4,33.05 56.83,33.62 56.83,35.06 57.21,35.43 64.39,35.43 64.9,34.92 64.9,34.29 65.66,33.53
N17123334 on TOP: 19.37,5.94 19.56,5.94 19.56,6.1 19.68,5.97 20.07,5.97 20.32,6.22 26.16,6.22 26.16,5.08 19.68,5.08 19.37,5.4
N17123833 on TOP: 20.7,9.4 22.86,9.4 24.64,11.18 26.16,11.18 26.16,12.19 24.38,12.19 22.1,9.91 21.59,9.91 21.21,9.53 20.7,9.53
N28614111 on BOTTOM: 36.2,24.26 36.2,19.15 35.91,19.15 35.05,18.3 35.05,16.26 35.09,16.23 37.94,16.23 38.1,16.38 38.1,18.16 38.67,18.73 38.67,19.37 40.01,20.7 40.01,24.13 39.88,24.26 36.7,24.26 36.58,24.13 36.32,24.13

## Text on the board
BOTTOM: PN#3H0013 | LAYER 6  SECONDARY SIDE | 6
Ref Des/Silkscreen Bottom: 1 | MMC0/SD | LCD | SYS BOOT | JTAG | GND | 24V-IN | 125VDC, | SLOW BLOW | 4A | 125VAC,
User.Comments: PCB-002
TOP: LAYER 1 - PRIMARY SIDE | 1 | 6
Ref Des/Assembly Top: Assembly marking must match with marking in physical component(pin 4) | This marking does not refer pin1 | Note: | 1
Ref Des/Silkscreen Top: USB | GND | WARMRST | VDAC | 1 | VAUX33 | A | VCAN | GNDPROFI | VPROFI | PROFIBUS_A | CAN_GND/ | VAUX2 | VRTC | SPEED_LED | ETH_1 | SYS BOOT | VDDA_ADC | RMII | ETH1_MODE | MII | ETH0_MODE | SYSBOOT | SPEED-LED | SEQ. | ETH_0 | VDD_LED | PROFINET | ETHERNET | LEDS | ON | CAN_PROFIBUS | VDDS_DDR | HOST EXP 2 | HOST EXP 1 | ETH SLAVE ADD | VMMC | VAUX1 | Ethernet_1 | POWER | VDD2_SMPS_AM335X | VDD1_SMPS | _AM335X | V3_3D | Ethernet_0 | IO EXP 3 | DIGITAL OUTPUTS | 24VDC | 2.5A | SN#:__________ | ASSM PN#:4P0025 | ARM MPU | AM335X ICE BOARD | REV 2.1A | UL 94V0 | LCD DISPLAY
PAGE_OUTLINE: UNLESS OTHERWISE SPECIFIED | DIMENSIONS ARE IN INCH | TOLERANCES ON; | 2 PL DECIMALS + | 3 PL DECIMALS + | ANGLES + | FRACTIONS + | LAYOUT BY | REVIEWED BY | APPROVED BY | SIGNATURES | DATE | 2.0 A | 2.1 A | REV | ICE_V2 | ICE_V2_1 | DESCRIPTION | SCALE | SIZE | 1:1 | 11-06-12 | 04-18-12 | APPROVED | AM335x_ICE_3H0013_REV_2_1A | TEXAS INSTRUMENTS
User.8: SPC     (TOP PASTEMASK)
User.9: SPS     (BOTTOM PASTEMASK)
User.11: 2 | ASSEMBLY BOTTOM
User.12: ASSEMBLY TOP | 1 | 2
User.15: FABRICATION DRAWING | 1 | 2x45
User.16: LAYER 2 - GROUND PLANE | 2 | 6
User.17: LAYER 3 - SIGNAL LAYER 1 | 3 | 6
User.18: LAYER 4 - SIGNAL LAYER 2 | 4 | 6
User.19: LAYER 5 - POWER LAYER | 5 | 6
User.20: SOLDER MASK BOTTOM | 2
User.21: SOLDER MASK TOP | 1 | 2
User.22: SOLDER PASTE BOTTOM | 2
User.23: SOLDER PASTE TOP | 1 | 2
User.24: SILKSCREEN BOTTOM | 2
User.25: SILKSCREEN TOP | 1 | 2
User.28: TOP SIDE VIEW | BOTTOM SIDE VIEW
User.32: BOARD NAME: | BOARD NO: 3H0013 | CUSTOMER NAME: | ICE | TEXAS INSTRUMENTS | REV: 2.1A | DESCRIPTION: | DATE: 04/18/2013 | SH | OF
User.33: OF | SH | DATE:04/18/2013 | DESCRIPTION: | TEXAS INSTRUMENTS | REV:2.1A | ICE | BOARD NAME: | CUSTOMER NAME: | BOARD NO:3H0013
User.34: L1_TOP | L3_SIG1 | L4_SIG2 | L6_BOTTOM | LAYERS | (mils) | SINGLE-ENDED | TRACE | WIDTH | 4.75 | 5.0 | +/-10% | TARGET | Ohms | 50 | 5.1 | EDGE-COUPLED DIFFERENTIAL | SPACE | 6.9 | 90 | 4.0 | 8.0 | 100
User.45: 4. APPLY LPI SILKSCREEN OR EQUIVALENT PER THE ARTWORK. | COLOR: WHITE. | SOLDERMASK PADS TO MEET THEIR TOOLING REQUIREMENTS. | FABRICATION VENDOR IS ALLOWED TO ADJUST THE COMPONENT | CONFORM TO IPC-SM-840, CLASS H. CURRENT REV. | 3. SOLDERMASK ARTWORK HAS ZERO (0) OVERSIZED PADS. | 2. APPLY LPI SOLDERMASK OVER BARE COPPER (SMOBC), | COLOR: MID GREY. SOLDERMASK SHALL | IMMERSION GOLD, NICKEL 150 MICROINCHES THK MIN | FINISHED AS SMOOTH WALL BY VEDOR. | GOLD 5-15 MICROINCHES THK MIN. | PROCESS NOTES: | 1. PLATE ALL EXPOSED AREAS WITH ELECTROLESS | 9. ALL VIAS TO HAVE SOLDERMASK. | FLAMMABILITY RATING 94V-0 AND IT SHOULD BE MARKED ON BOARD. | 4. BOARD MATERIAL & CONSTRUCTION SHOULD MEET OR EXCEED UL | FAB NOTES: | 1. ALL DIMENSIONS ARE IN INCHES, UNLESS | OTHERWISE NOTED. | 2. THE PWB SHALL BE FABRICATED TO IPC-6012, | CLASS 2 AND WORKMANSHIP SHALL CONFORM TO | IPC-A-600, CLASS 2. CURRENT REVISIONS. | 3. BOARD MATERIAL SHALL BE 180 Tg/350 Td ISOLA FR-370 HR | OR EQUIVALENT, RoHS COMPLIANT AND LEAD FREE | ASSEMBLY CAPABLE.  BOARD MATERIAL SHALL | MEET OR EXCEED IPC-4101B. COLOR: NATURAL. | 5. MINIMUM COPPER WALL THICKNESS OF PLATED-THRU | HOLES TO BE .001 INCH, WITH A MINIMUM | ANNULAR RING OF .002 INCH. | 6. OVERALL BOARD THICKNESS TO BE .063 +/- 10% | AND APPLIES AFTER ALL LAMINATION AND PLATING | PROCESSES, MEASURED FROM COPPER TO COPPER. | 7. MAX. WARP & TWIST TO BE .0075 INCHES PER INCH. | 8. BOARD MUST BE ELECTRICALLY TESTED USING | SUPPLIED IPC-D-356 NETLIST. | NOTE : | IMPEDANCE REQUIREMENT :- THIS DESIGN MAY NOT CONTAIN ALL THE FEATURES | LISTED IN THE ABOVE TABLE | FIGURE | SIZE | 8.0 | 12.0 | 28.0 | 35.0 | 35.04 | 40.0 | 40.16 | 50.0 | 67.0 | 120.0 | 138.0 | 140.0 | 59.0 | 125.98 | DRILL CHART: TOP to BOTTOM | ALL UNITS ARE IN MILS | TOLERANCE | +3.0/-3.0 | +0.0/-0.0 | +7.87/-7.87 | +5.0/-5.0 | +3.94/-3.94 | PLATED | NON-PLATED | QTY | 1028 | 506 | 12 | 58 | 16 | 6 | 4 | 38 | 2 | 1
